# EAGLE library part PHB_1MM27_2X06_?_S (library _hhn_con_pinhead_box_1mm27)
Pin Header Box-Type, 1.27mm/0.5"/50mil Pitch, 2x06 Circuits, single gates in schematic Note: see library description for an important note about THT-version
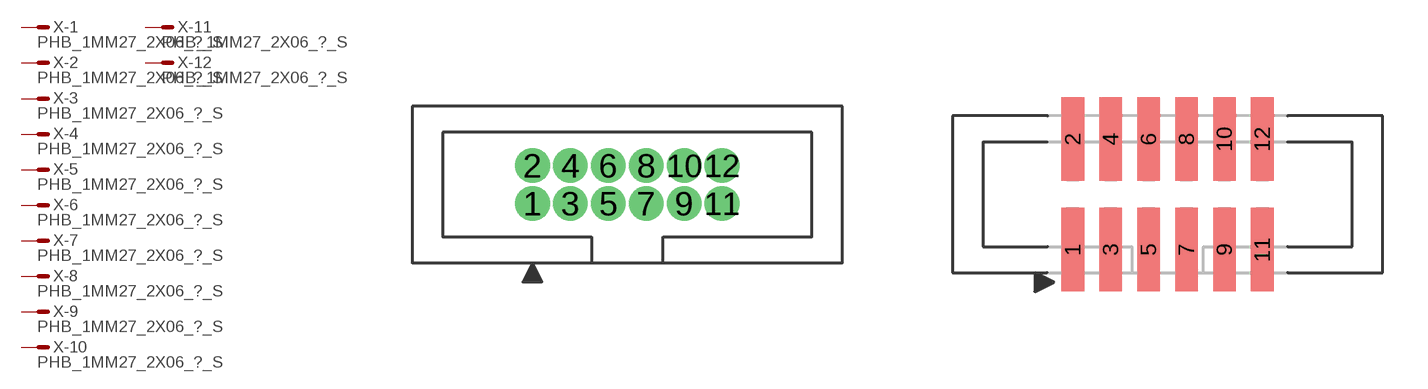
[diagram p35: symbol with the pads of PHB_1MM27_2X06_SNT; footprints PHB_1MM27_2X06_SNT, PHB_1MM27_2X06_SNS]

Designator prefix X; gates -1=M -2=M -3=M -4=M -5=M -6=M -7=M -8=M -9=M -10=M -11=M -12=M

## PHB_1MM27_2X06_SNT_S  [PHB_1MM27_2X06_SNT]
1  -1:S  pas
2  -2:S  pas
3  -3:S  pas
4  -4:S  pas
5  -5:S  pas
6  -6:S  pas
7  -7:S  pas
8  -8:S  pas
9  -9:S  pas
10  -10:S  pas
11  -11:S  pas
12  -12:S  pas

## PHB_1MM27_2X06_SNS_S  [PHB_1MM27_2X06_SNS]
Pads as for PHB_1MM27_2X06_SNT

## Footprint PHB_1MM27_2X06_SNT (pad centres in mm)
Pin Header Box-Type, 1.27mm Pitch, 2x06 circuits, Straight, No Locking, THT Important Note: Diameter in this lbr is set to a specific value (NOT 'auto' = 0), this is ignored by actual eagle versions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
drill 0.65 pad 1 round: 1 -3.175,-0.635; 2 -3.175,0.635; 3 -1.905,-0.635; 4 -1.905,0.635; 5 -0.635,-0.635; 6 -0.635,0.635; 7 0.635,-0.635; 8 0.635,0.635; 9 1.905,-0.635; 10 1.905,0.635; 11 3.175,-0.635; 12 3.175,0.635

## Footprint PHB_1MM27_2X06_SNS (pad centres in mm)
Pin Header Box-Type, 1.27mm Pitch, 2x06 circuits, Straight, No Locking, SMT
smd 0.76 x 2.8: 1 -3.175,-1.85; 2 -3.175,1.85; 3 -1.905,-1.85; 4 -1.905,1.85; 5 -0.635,-1.85; 6 -0.635,1.85; 7 0.635,-1.85; 8 0.635,1.85; 9 1.905,-1.85; 10 1.905,1.85; 11 3.175,-1.85; 12 3.175,1.85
